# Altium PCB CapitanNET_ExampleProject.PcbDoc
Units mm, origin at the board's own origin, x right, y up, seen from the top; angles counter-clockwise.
Board outline 171.38 x 171.4 mm, 6 copper layers (Top Layer, Mid-Layer 1, Mid-Layer 2, Mid-Layer 3, Mid-Layer 4, Bottom Layer), stack 1.53 mm thick; 13 components, 61 nets, 307 pads, 51 vias.
Unrouted connection lines stored in the file: 9.
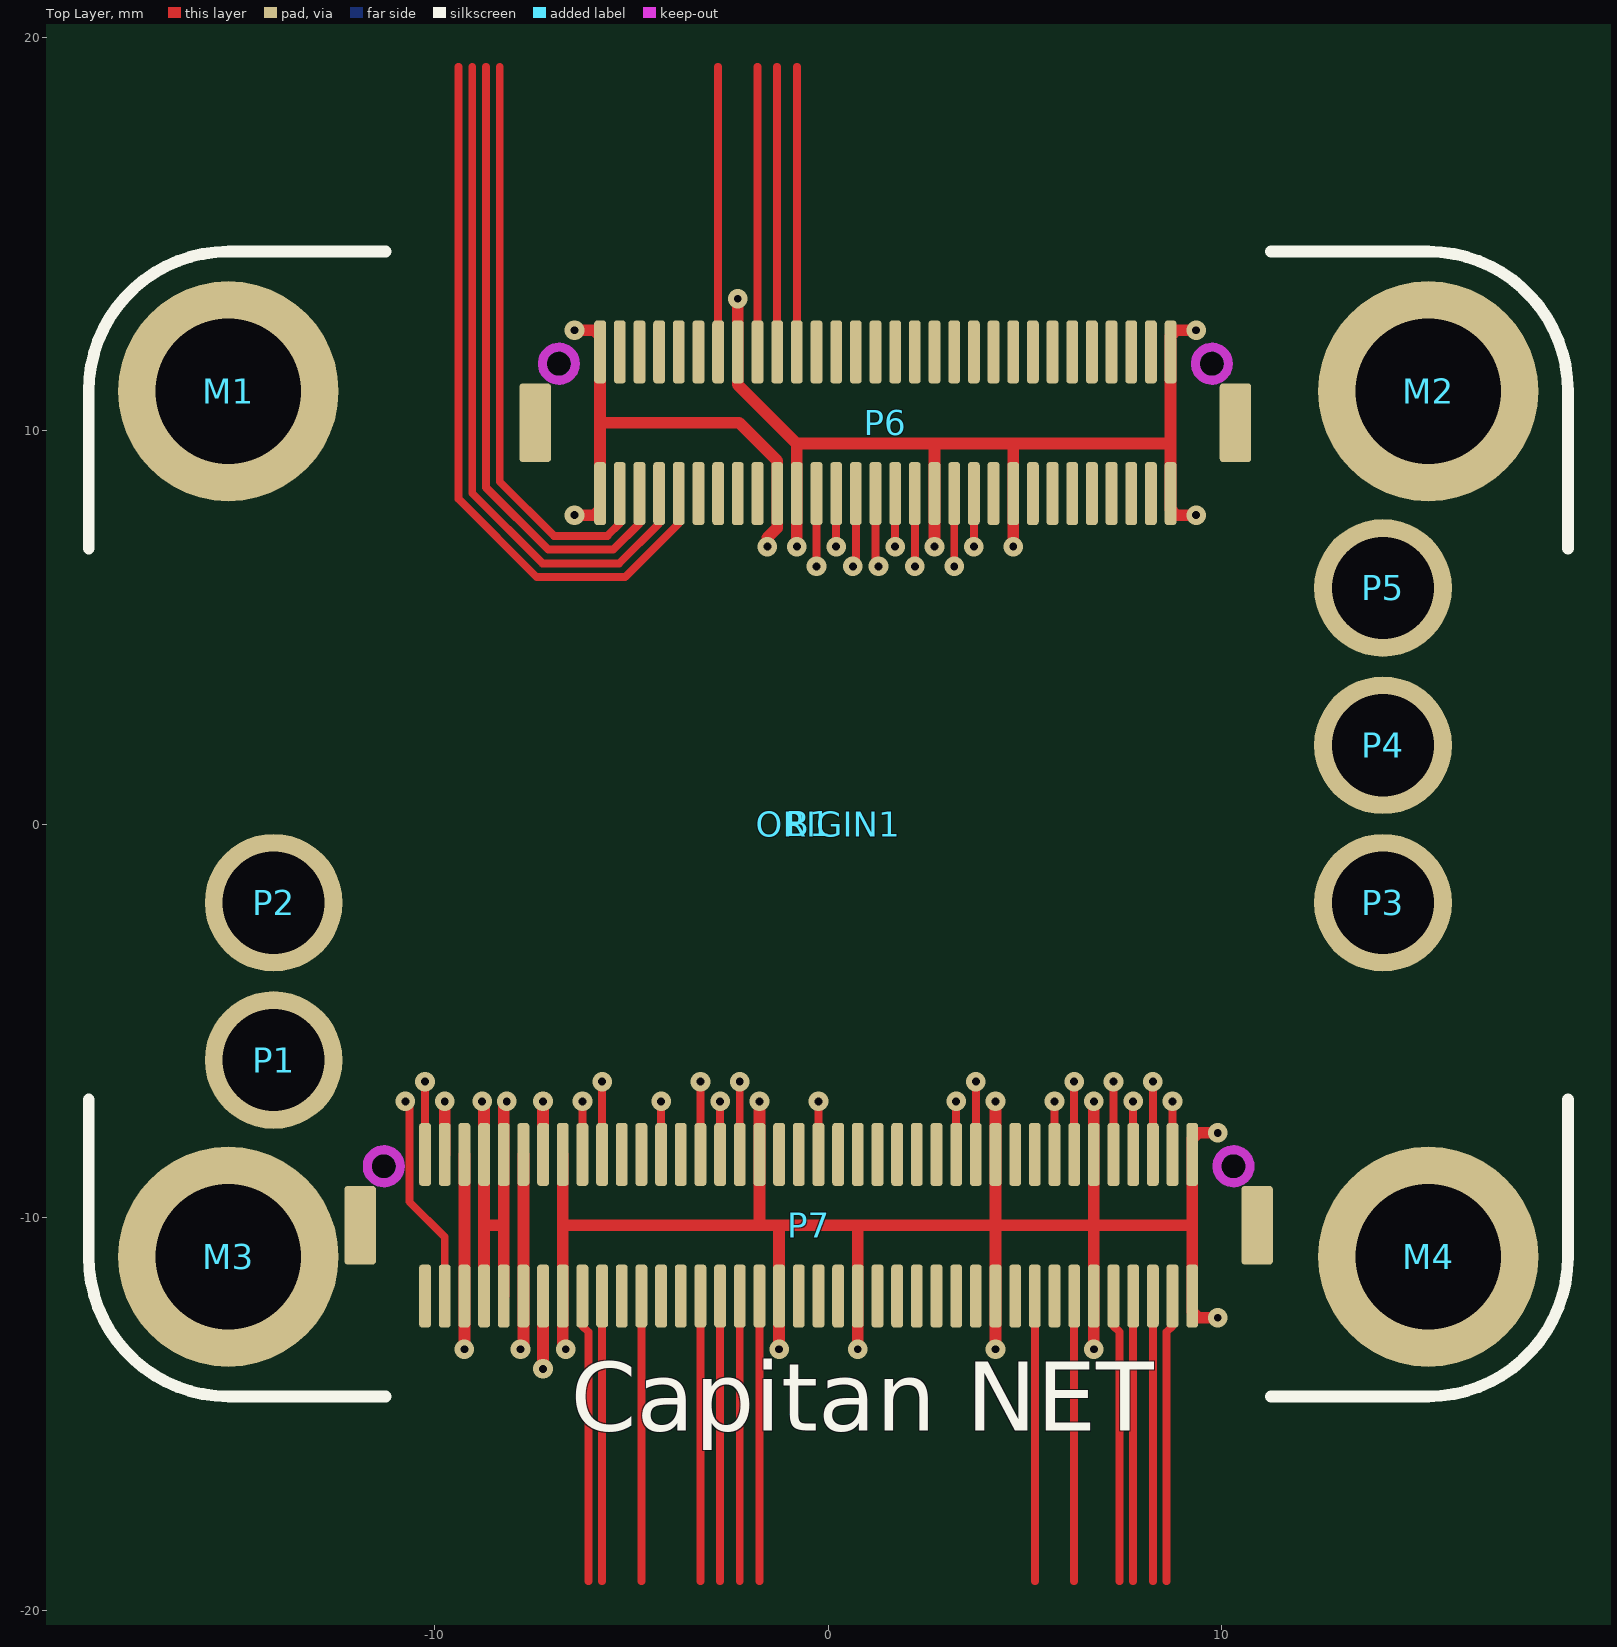
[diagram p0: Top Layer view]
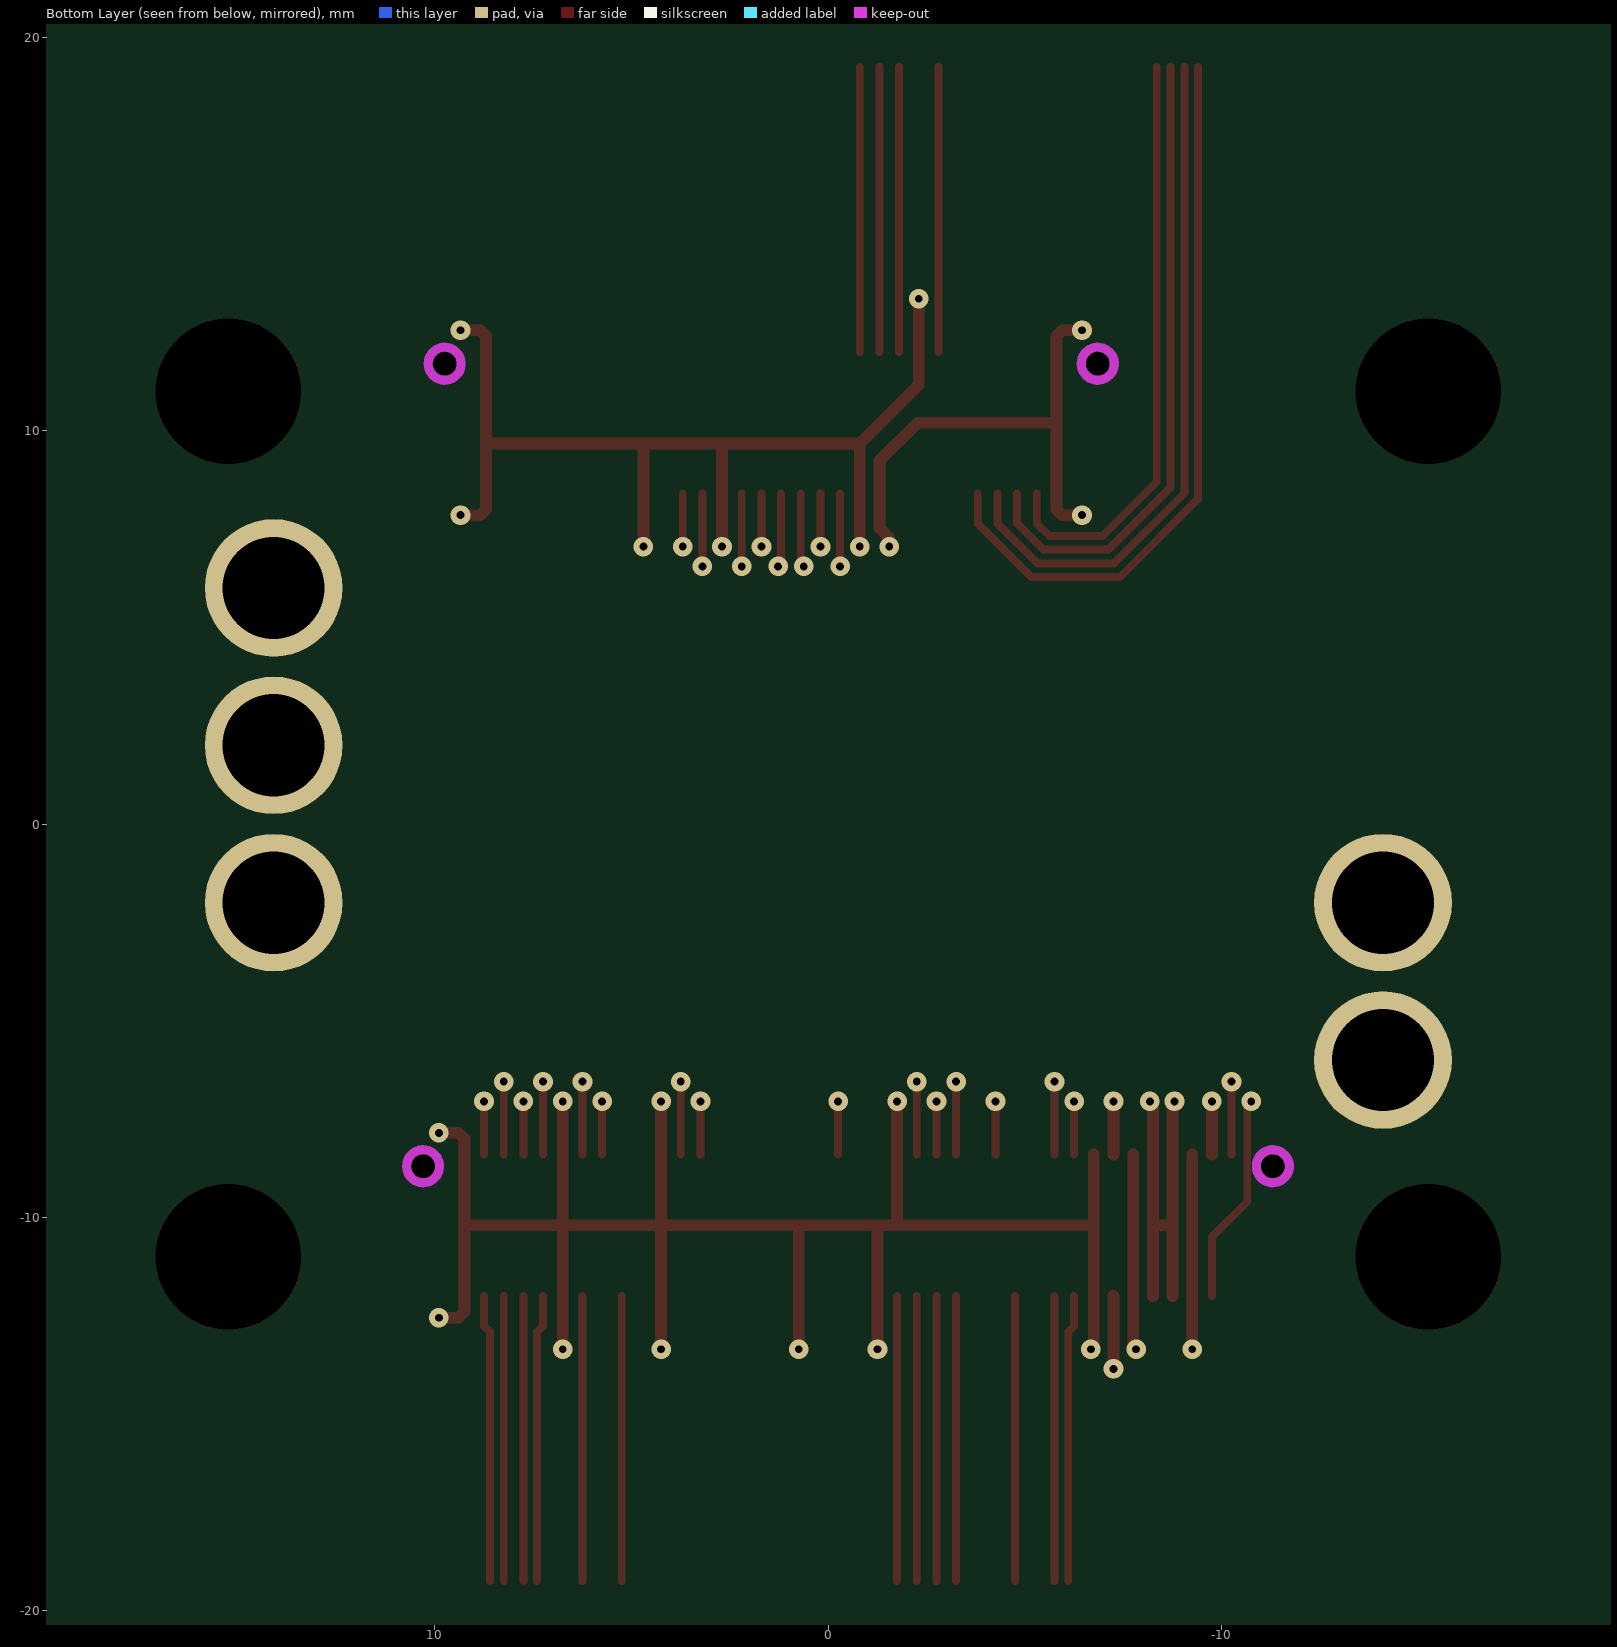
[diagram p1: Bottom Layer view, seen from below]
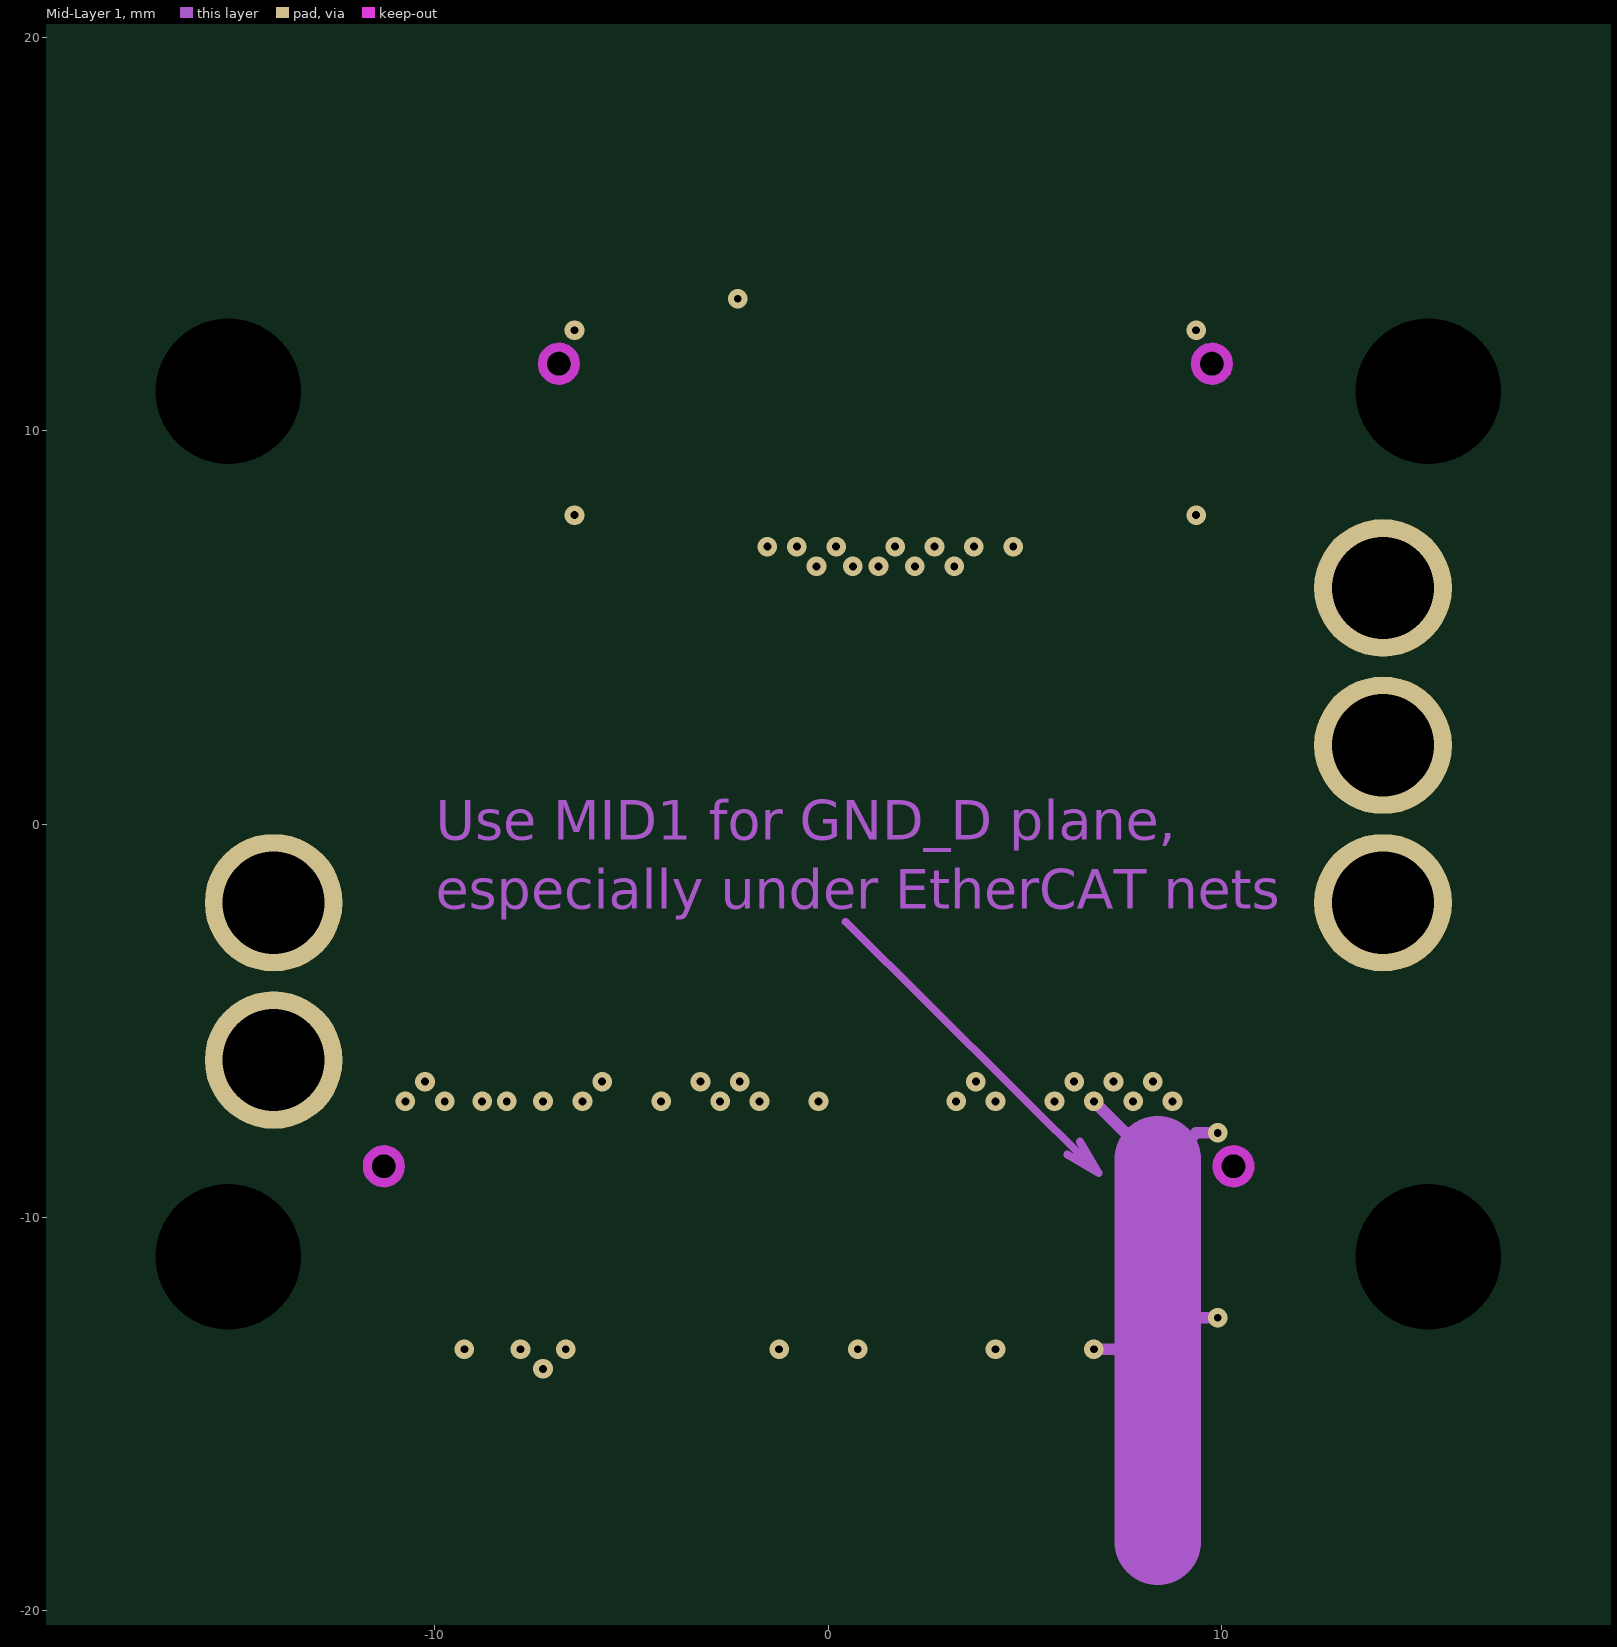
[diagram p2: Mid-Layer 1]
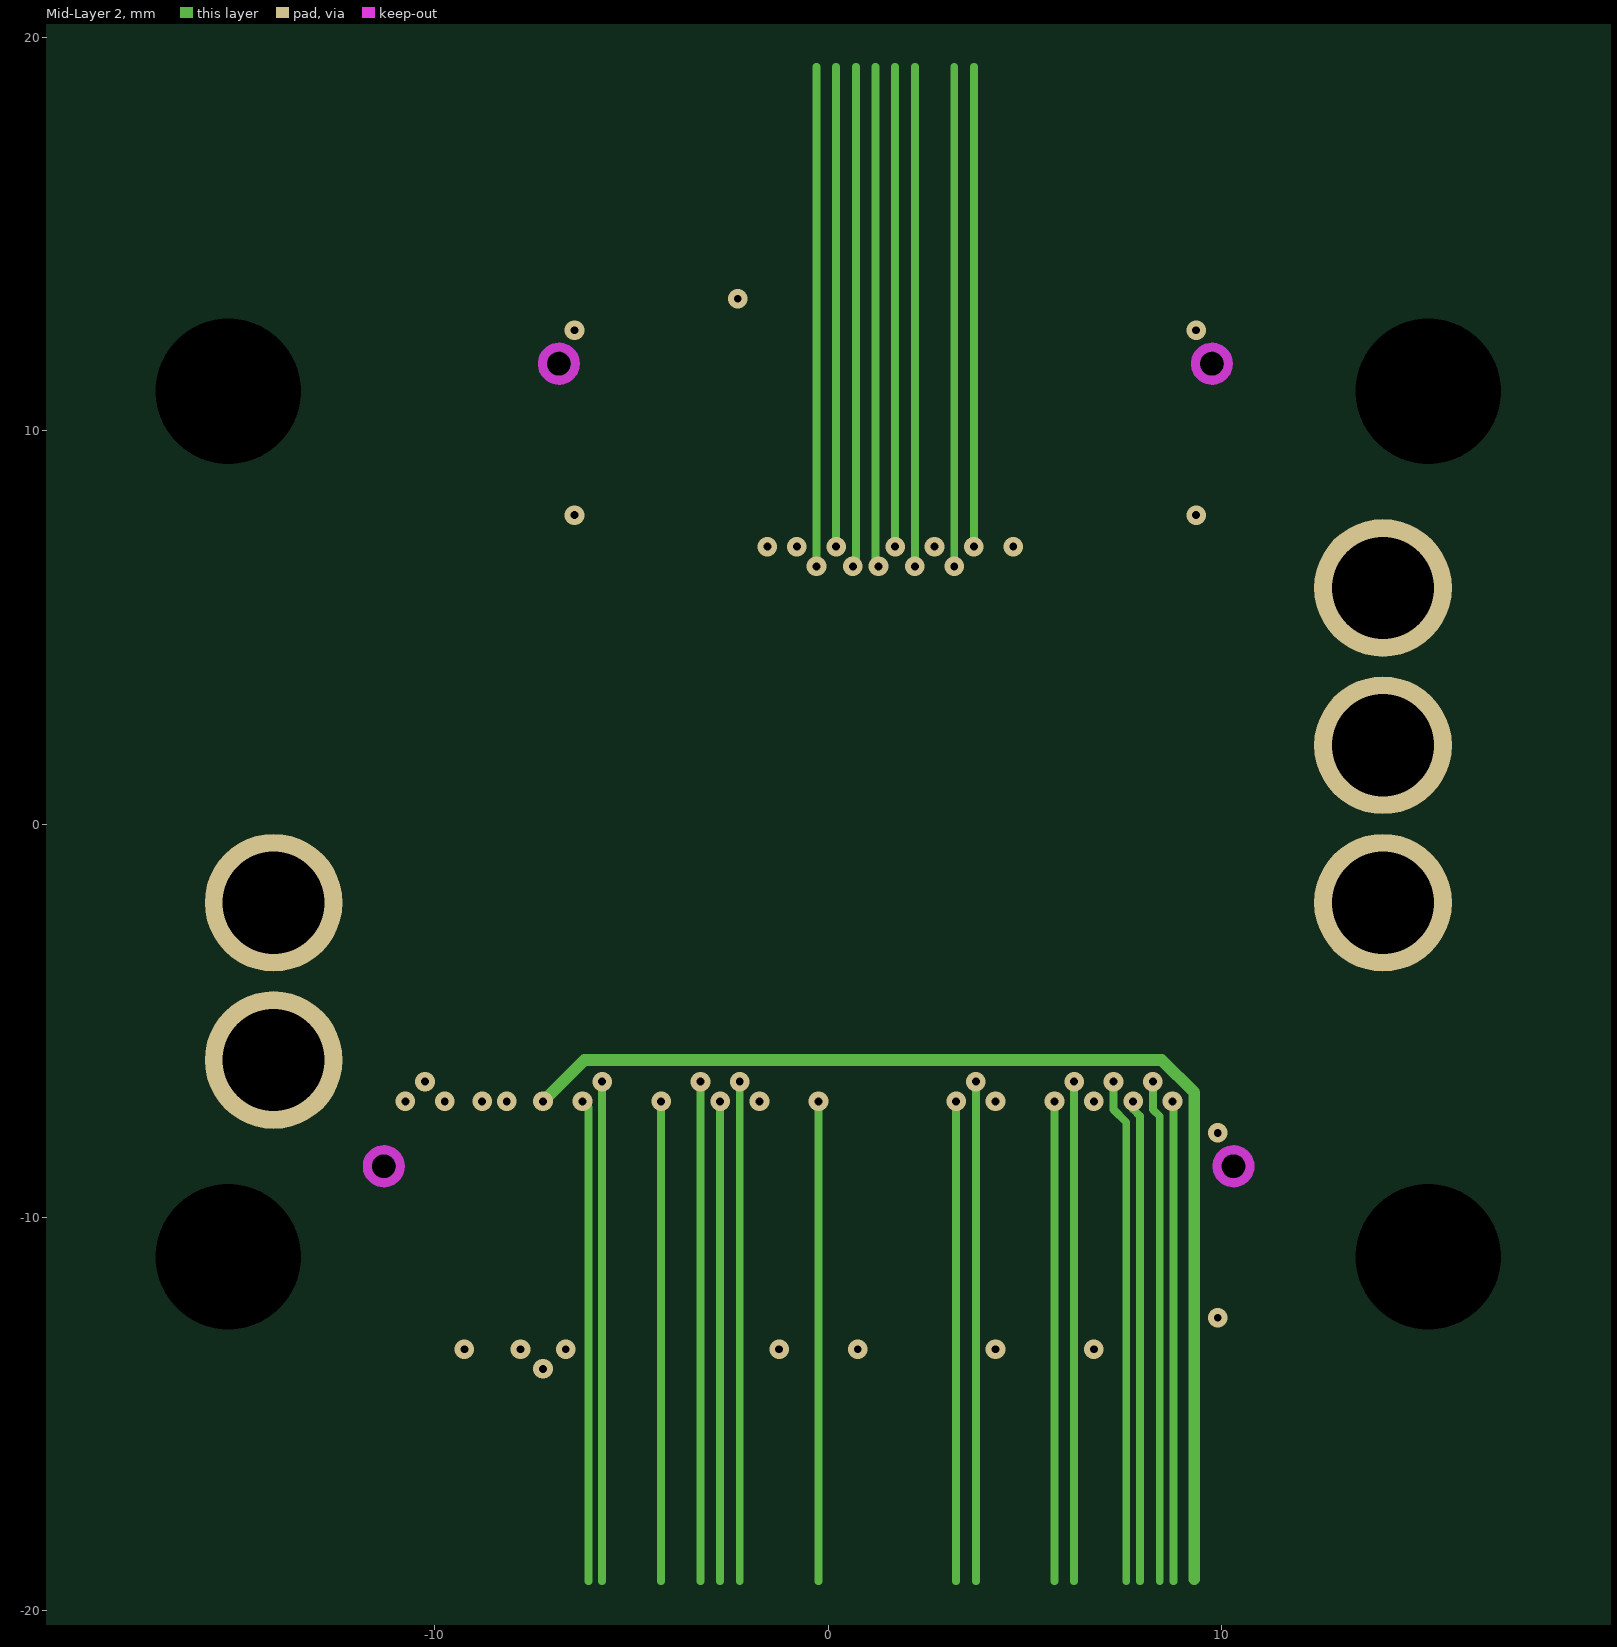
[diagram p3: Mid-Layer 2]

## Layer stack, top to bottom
Top Solder: solder mask 0.01, Solder Resist, Dk 3.5
Top Layer: signal copper 0.035
Dielectric1: prepreg 0.13, FR-4, Dk 4.8
Mid-Layer 1: signal copper 0.07
Dielectric2: core 0.35, FR-4, Dk 4.8
Mid-Layer 2: signal copper 0.07
Dielectric3: prepreg 0.22, FR-4, Dk 4.8
Mid-Layer 3: signal copper 0.07
Dielectric4: core 0.35, FR-4, Dk 4.8
Mid-Layer 4: signal copper 0.07
Dielectric5: prepreg 0.13, FR-4, Dk 4.8
Bottom Layer: signal copper 0.035
Bottom Solder: solder mask 0.01, Solder Resist, Dk 3.5

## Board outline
-87.181,-84.732 84.194,-84.732 84.194,86.668 -87.181,86.668

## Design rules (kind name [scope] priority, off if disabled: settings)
AssemblyTestPointUsage [All] p1 off: valid=2
AssemblyTestpoint [All] p1 off: testpointundercomponent=TRUE minsize=1.016 maxsize=2.54 preferedsize=1.524 minholesize=0 maxholesize=1.016 preferedholesize=0.813 testpointgrid=0.025 usegrid=TRUE gridtolerance=0 allowsidetop=TRUE allowsidebottom=TRUE
Clearance "Keepout clearance" [All vs OnLayer('Keep-Out Layer') Or IsKeepOut Or Keepout] p1: gap=0.001 ignorepadtopadclearanceinfootprint=FALSE
Clearance HV [InNetClass('HighVoltage') vs OnOutside And NOT InNetClass('HighVoltageFloating')] p2: gap=0.5 ignorepadtopadclearanceinfootprint=TRUE
Clearance Clearance_PE [InNetClass('ProtectiveEarth')] p3: gap=0.5 ignorepadtopadclearanceinfootprint=TRUE
Clearance General [All] p4: gap=0.15 ignorepadtopadclearanceinfootprint=TRUE
ComponentClearance ComponentClearance_Excluded [All vs InComponent ('B1') OR InComponent('P1') OR InComponent('P2') OR InComponent('P3') OR InComponent('P4') OR InComponent('P5') OR InComponent('P6') OR InComponent('P7') OR InComponent('H1') OR InComponent('H2') OR InComponent('H3') OR InComponent('H4') OR InComponent('H5') OR InComponent('M1') OR InComponent('M2') OR InComponent('M3') OR InComponent('M4')] p1: gap=0 collisioncheckmode=3 verticalgap=0 showdistances=FALSE
ComponentClearance [All] p2: gap=0.2 collisioncheckmode=3 verticalgap=0.2 showdistances=FALSE
DiffPairsRouting [All] p1: maxlimit=1 minlimit=0.15 mostfreqgap=0.2 toplayer_minwidth=0.15 toplayer_maxwidth=0.3 toplayer_prefwidth=0.2 midlayer1_minwidth=0.15 midlayer1_maxwidth=0.3 midlayer1_prefwidth=0.2 midlayer2_minwidth=0.15 midlayer2_maxwidth=0.3 midlayer2_prefwidth=0.2 midlayer3_minwidth=0.15 midlayer3_maxwidth=0.3 midlayer3_prefwidth=0.2 midlayer4_minwidth=0.15 midlayer4_maxwidth=0.3 midlayer4_prefwidth=0.2 bottomlayer_minwidth=0.15 bottomlayer_maxwidth=0.3 bottomlayer_prefwidth=0.2 maxuncoupledlength=12.7
FabricationTestPointUsage [All] p1 off: valid=0 allowmultiple=FALSE
FabricationTestpoint [All] p1 off: side=3 testpointundercomponent=TRUE minsize=1.016 maxsize=2.54 preferedsize=1.524 minholesize=0 maxholesize=1.016 preferedholesize=0.813 testpointgrid=0.025 allowsidetop=TRUE allowsidebottom=TRUE usegrid=TRUE gridtolerance=0
FanoutControl Fanout_BGA [IsBGA] p1 off: bgadir=Out bgaviamode=Centered fanoutstyle=Auto fanoutdirection=Alternating viagrid=0.025 // Fanout_BGA (Default Rule)
FanoutControl Fanout_LCC [IsLCC] p2 off: bgadir=Out bgaviamode=Centered fanoutstyle=Auto fanoutdirection=Alternating viagrid=0.025 // Fanout_LCC (Default Rule)
FanoutControl Fanout_SOIC [IsSOIC] p3 off: bgadir=Out bgaviamode=Centered fanoutstyle=Auto fanoutdirection=Alternating viagrid=0.025 // Fanout_SOIC (Default Rule)
FanoutControl Fanout_Small [(CompPinCount < 5)] p4 off: bgadir=Out bgaviamode=Centered fanoutstyle=Auto fanoutdirection=OutThenIn viagrid=0.025 // Fanout_Small (Default Rule)
FanoutControl Fanout_Default [All] p5 off: bgadir=Out bgaviamode=Centered fanoutstyle=Auto fanoutdirection=Alternating viagrid=0.025 // Fanout_Default (Default Rule)
Height [All] p1: minheight=0 maxheight=30 prefheight=12.7
HoleSize [All] p1: absolutevalues=TRUE maxlimit=5 minlimit=0.1 maxpercent=80.000 minpercent=20.000
HoleToHoleClearance [All] p1: gap=0.3 allowstackedmicrovias=FALSE
MinimumAnnularRing [All] p1: minimumring=0.1
MinimumSolderMaskSliver [All] p1: minsoldermaskwidth=0.07
NetAntennae [All] p1: netantennaetolerance=2
PlaneClearance [All] p1: clearance=0.25
PlaneConnect [All] p1: planeconnectstyle=Relief reliefexpansion=0.5 reliefentries=4 reliefconductorwidth=0.25 reliefairgap=0.25
PolygonConnect [All] p1: connectstyle=Direct reliefconductorwidth=0.25 reliefentries=4 polygonreliefangle="90 Angle" airgapwidth=0.25
RoomDefinition U_CapitanNET_Module [InComponentClass('U_CapitanNET_Module')] p1: confinementstyle=ConfineIn formatcopy=TRUE lockcomponents=FALSE outline -155.261,-141.812 -104.461,-141.812 -104.461,-116.412 -155.261,-116.412
RoutingVias [All] p1: holewidth=0.2 width=0.6 viastyle="Through Hole" minholewidth=0.1 minwidth=0.3 maxholewidth=1 maxwidth=1.5
SilkToSilkClearance [All] p1 off: silktosilkclearance=0.1
SilkToSolderMaskClearance SilkscreenOverComponentPads [IsPad] p1 off: minsilkscreentomaskgap=0.05 clearancetoexposedcopper=TRUE
SolderMaskExpansion [All] p1: expansion=0.05 istentingtop=FALSE
UnRoutedNet [All] p1: checkbadconnections=TRUE
Width [All] p1: maxlimit=80 minlimit=0.15 preferedwidth=0.2 checkconnectedcopper=TRUE
9 further rules are at their usual default settings.

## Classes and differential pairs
component class Top: ORIGIN1
net class ProtectiveEarth: PE1 PE2 PE3 PE4
net class HighVoltage: GND_P PH_A PH_B PH_C POW_SUP
net class HighCurrent: GND_P PH_A PH_B PH_C POW_SUP
component class U_CapitanNET_Module: B1 M1 M2 M3 M4 P1 P2 P3 P4 P5 P6 P7

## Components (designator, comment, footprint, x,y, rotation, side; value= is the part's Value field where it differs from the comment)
B1 "Capitan_NET" CAPITAN_NET 0,0 r0 top value=-
M1 "Part Number" WURTH_9774030951R -15.25,11 r0 top value=-
M2 "Part Number" WURTH_9774030951R 15.25,11 r0 top value=-
M3 "Part Number" WURTH_9774030951R -15.25,-11 r0 top value=-
M4 "WURTH_9774030951R" WURTH_9774030951R 15.25,-11 r0 top value=-
ORIGIN1 "ORIGIN" ORIGIN 0,0 r0 top value=-
P1 "Part Number" MillMax_9801-0-15-15-23-27-10-0 -14.1,-6 r0 top value=-
P2 "Part Number" MillMax_9801-0-15-15-23-27-10-0 -14.1,-2 r0 top value=-
P3 "Part Number" MillMax_9801-0-15-15-23-27-10-0 14.1,-2 r0 top value=-
P4 "Part Number" MillMax_9801-0-15-15-23-27-10-0 14.1,2 r0 top value=-
P5 "Part Number" MillMax_9801-0-15-15-23-27-10-0 14.1,6 r0 top value=-
P6 "HIROSE_DF12NB_(3.0)-60DS-0.5V_(51)" HIROSE_DF12NB(3.0)-60DS-0.5V(51) 1.45,10.2 r0 top value=-
P7 "HIROSE_DF12NB(3.0)-80DS-0.5V(51)" HIROSE_DF12NB(3.0)-80DS-0.5V(51) -0.5,-10.2 r0 top value=-

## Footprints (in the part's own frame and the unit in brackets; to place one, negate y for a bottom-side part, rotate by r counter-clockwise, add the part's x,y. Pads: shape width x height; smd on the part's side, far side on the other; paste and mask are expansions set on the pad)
CAPITAN_NET [mm] "Capitan NET 3D model + Pads + Connectors position"
  rrect20% 0.8x2 on Mech5: 0(-11.9,-10.2) 0(-7.45,10.2) 0(10.35,10.2) 0(10.9,-10.2)
  rrect50% 0.3x1.6 on Mech5: 1(-10.25,-8.4) 1(-5.8,12) 2(-10.25,-12) 2(-5.8,8.4) 3(-9.75,-8.4) 3(-5.3,12) 4(-9.75,-12) 4(-5.3,8.4) 5(-9.25,-8.4) 5(-4.8,12) 6(-9.25,-12) 6(-4.8,8.4) 7(-8.75,-8.4) 7(-4.3,12) 8(-8.75,-12) 8(-4.3,8.4) 9(-8.25,-8.4) 9(-3.8,12) 10(-8.25,-12) 10(-3.8,8.4) 11(-7.75,-8.4) 11(-3.3,12) 12(-7.75,-12) 12(-3.3,8.4) 13(-7.25,-8.4) 13(-2.8,12) 14(-7.25,-12) 14(-2.8,8.4) 15(-6.75,-8.4) 15(-2.3,12) 16(-6.75,-12) 16(-2.3,8.4) 17(-6.25,-8.4) 17(-1.8,12) 18(-6.25,-12) 18(-1.8,8.4) 19(-5.75,-8.4) 19(-1.3,12) 20(-5.75,-12) 20(-1.3,8.4) 21(-5.25,-8.4) 21(-0.8,12) 22(-5.25,-12) 22(-0.8,8.4) 23(-4.75,-8.4) 23(-0.3,12) 24(-4.75,-12) 24(-0.3,8.4) 25(-4.25,-8.4) 25(0.2,12) 26(-4.25,-12) 26(0.2,8.4) 27(-3.75,-8.4) 27(0.7,12) 28(-3.75,-12) 28(0.7,8.4) 29(-3.25,-8.4) 29(1.2,12) 30(-3.25,-12) 30(1.2,8.4) 31(-2.75,-8.4) 31(1.7,12) 32(-2.75,-12) 32(1.7,8.4) 33(-2.25,-8.4) 33(2.2,12) 34(-2.25,-12) 34(2.2,8.4) 35(-1.75,-8.4) 35(2.7,12) 36(-1.75,-12) 36(2.7,8.4) 37(-1.25,-8.4) 37(3.2,12) 38(-1.25,-12) 38(3.2,8.4) 39(-0.75,-8.4) 39(3.7,12) 40(-0.75,-12) 40(3.7,8.4) 41(-0.25,-8.4) 41(4.2,12) 42(-0.25,-12) 42(4.2,8.4) 43(0.25,-8.4) 43(4.7,12) 44(0.25,-12) 44(4.7,8.4) 45(0.75,-8.4) 45(5.2,12) 46(0.75,-12) 46(5.2,8.4) 47(1.25,-8.4) 47(5.7,12) 48(1.25,-12) 48(5.7,8.4) 49(1.75,-8.4) 49(6.2,12) 50(1.75,-12) 50(6.2,8.4) 51(2.25,-8.4) 51(6.7,12) 52(2.25,-12) 52(6.7,8.4) 53(2.75,-8.4) 53(7.2,12) 54(2.75,-12) 54(7.2,8.4) 55(3.25,-8.4) 55(7.7,12) 56(3.25,-12) 56(7.7,8.4) 57(3.75,-8.4) 57(8.2,12) 58(3.75,-12) 58(8.2,8.4) 59(4.25,-8.4) 59(8.7,12) 60(4.25,-12) 60(8.7,8.4) 61(4.75,-8.4) 62(4.75,-12) 63(5.25,-8.4) 64(5.25,-12) 65(5.75,-8.4) 66(5.75,-12) 67(6.25,-8.4) 68(6.25,-12) 69(6.75,-8.4) 70(6.75,-12) 71(7.25,-8.4) 72(7.25,-12) 73(7.75,-8.4) 74(7.75,-12) 75(8.25,-8.4) 76(8.25,-12) 77(8.75,-8.4) 78(8.75,-12) 79(9.25,-8.4) 80(9.25,-12)
  silkscreen extent -18.8,-14.55 18.8,14.55, body extent -17.25,-13 17.25,13, height 11
HIROSE_DF12NB(3.0)-60DS-0.5V(51) [mm] "CONN HEADER BLACK 60POS 5MM SMD 0.5MM"
  rrect50% 0.3x1.6 smd: 1(-7.25,1.8) 2(-7.25,-1.8) 3(-6.75,1.8) 4(-6.75,-1.8) 5(-6.25,1.8) 6(-6.25,-1.8) 7(-5.75,1.8) 8(-5.75,-1.8) 9(-5.25,1.8) 10(-5.25,-1.8) 11(-4.75,1.8) 12(-4.75,-1.8) 13(-4.25,1.8) 14(-4.25,-1.8) 15(-3.75,1.8) 16(-3.75,-1.8) 17(-3.25,1.8) 18(-3.25,-1.8) 19(-2.75,1.8) 20(-2.75,-1.8) 21(-2.25,1.8) 22(-2.25,-1.8) 23(-1.75,1.8) 24(-1.75,-1.8) 25(-1.25,1.8) 26(-1.25,-1.8) 27(-0.75,1.8) 28(-0.75,-1.8) 29(-0.25,1.8) 30(-0.25,-1.8) 31(0.25,1.8) 32(0.25,-1.8) 33(0.75,1.8) 34(0.75,-1.8) 35(1.25,1.8) 36(1.25,-1.8) 37(1.75,1.8) 38(1.75,-1.8) 39(2.25,1.8) 40(2.25,-1.8) 41(2.75,1.8) 42(2.75,-1.8) 43(3.25,1.8) 44(3.25,-1.8) 45(3.75,1.8) 46(3.75,-1.8) 47(4.25,1.8) 48(4.25,-1.8) 49(4.75,1.8) 50(4.75,-1.8) 51(5.25,1.8) 52(5.25,-1.8) 53(5.75,1.8) 54(5.75,-1.8) 55(6.25,1.8) 56(6.25,-1.8) 57(6.75,1.8) 58(6.75,-1.8) 59(7.25,1.8) 60(7.25,-1.8)
  round 0 hole 0.6 unplated: H1(-8.3,1.5) H2(8.3,1.5)
  rrect20% 0.8x2 smd: S1(-8.9,0) S2(8.9,0)
  Keep-Out Layer circle w0.23: c8.3,1.5 r0.42
  Keep-Out Layer circle w0.23: c-8.3,1.5 r0.42
  body extent -9.05,-2.3 9.05,2.3, height 2.2
HIROSE_DF12NB(3.0)-80DS-0.5V(51) [mm] "CONN HEADER 80POS 3MM SMD 0.5MM"
  rrect50% 0.3x1.6 smd paste-0.02 mask+0.05: 1(-9.75,1.8) 2(-9.75,-1.8) 3(-9.25,1.8) 4(-9.25,-1.8) 5(-8.75,1.8) 6(-8.75,-1.8) 7(-8.25,1.8) 8(-8.25,-1.8) 9(-7.75,1.8) 10(-7.75,-1.8) 11(-7.25,1.8) 12(-7.25,-1.8) 13(-6.75,1.8) 14(-6.75,-1.8) 15(-6.25,1.8) 16(-6.25,-1.8) 17(-5.75,1.8) 18(-5.75,-1.8) 19(-5.25,1.8) 20(-5.25,-1.8) 21(-4.75,1.8) 22(-4.75,-1.8) 23(-4.25,1.8) 24(-4.25,-1.8) 25(-3.75,1.8) 26(-3.75,-1.8) 27(-3.25,1.8) 28(-3.25,-1.8) 29(-2.75,1.8) 30(-2.75,-1.8) 31(-2.25,1.8) 32(-2.25,-1.8) 33(-1.75,1.8) 34(-1.75,-1.8) 35(-1.25,1.8) 36(-1.25,-1.8) 37(-0.75,1.8) 38(-0.75,-1.8) 39(-0.25,1.8) 40(-0.25,-1.8) 41(0.25,1.8) 42(0.25,-1.8) 43(0.75,1.8) 44(0.75,-1.8) 45(1.25,1.8) 46(1.25,-1.8) 47(1.75,1.8) 48(1.75,-1.8) 49(2.25,1.8) 50(2.25,-1.8) 51(2.75,1.8) 52(2.75,-1.8) 53(3.25,1.8) 54(3.25,-1.8) 55(3.75,1.8) 56(3.75,-1.8) 57(4.25,1.8) 58(4.25,-1.8) 59(4.75,1.8) 60(4.75,-1.8) 61(5.25,1.8) 62(5.25,-1.8) 63(5.75,1.8) 64(5.75,-1.8) 65(6.25,1.8) 66(6.25,-1.8) 67(6.75,1.8) 68(6.75,-1.8) 69(7.25,1.8) 70(7.25,-1.8) 71(7.75,1.8) 72(7.75,-1.8) 73(8.25,1.8) 74(8.25,-1.8) 75(8.75,1.8) 76(8.75,-1.8) 77(9.25,1.8) 78(9.25,-1.8) 79(9.75,1.8) 80(9.75,-1.8)
  round 0 hole 0.6 unplated: H1(-10.8,1.5) H2(10.8,1.5)
  rrect20% 0.8x2 smd: S1(-11.4,0) S2(11.4,0)
  Keep-Out Layer circle w0.23: c10.8,1.5 r0.42
  Keep-Out Layer circle w0.23: c-10.8,1.5 r0.42
  body extent -11.55,-2.3 11.55,2.3, height 2.2
MillMax_9801-0-15-15-23-27-10-0 [mm]
  round 3.5 hole 2.6: 1(0,0)
  body extent -1.52,-1.52 1.52,1.52, height 1.78
ORIGIN [mm] "Origin of coordinate axes for pick and place"
  round 0.5 on Mech10 paste+0 mask+0: 1(0,0) 1(0,0)
  round 0.5 on Mech16 paste+0 mask+0: 1(0,0) 1(0,0)
  round 0.5 on Mech11 paste+0 mask+0: 1(0,0) 1(0,0)
  body extent 0,0 0,0
WURTH_9774030951R [mm] "M2.5 SPACER Thread Internal, Length 3mm"
  round 5.6 / inner round 0 / far side round 0 hole 3.7 unplated paste-403.566: 1(0,0)
  body extent -2.55,-2.55 2.55,2.55, height 3.01

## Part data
B1: "Capitan NET high-performance Servo Drive from Ingenia Motion Control.", AlternativeManufacturer=Ingenia, ManufacturerPN=CAP-NET-E, Package Type=-, TemperatureMaxC=85, TemperatureMinC=-40
M1 M2 M3 M4: library part SPACER_SMD_ROUND_M2.5x3mm_NO_THREAD, "Round SMD standoff M2.5 3mm height No Threaded Steel", ManufacturerName="Wurth Electronics Inc", ManufacturerPN=9774030951R, Package Name="SPACER M2.5 SMD REEL 3MM", Package Type=SM, Supplier Part Number 1=732-7086-1-ND, TemperatureMaxC=200, TemperatureMinC=-40
ORIGIN1: "Origin of coordinate axes for pick and place", ManufacturerName=-, TemperatureMaxC=200, TemperatureMinC=-60
P1 P2 P3 P4 P5: library part MillMax_9801-0-15-15-23-27-10-0, "1pin, receptacle for MillMax 6142, blind end", ManufacturerName=MillMax, ManufacturerPN=9801-0-15-15-23-27-10-0, Package Type=TH, Supplier Part Number 1=ED1006-ND, TemperatureMaxC=125, TemperatureMinC=-55
P6: "Connector SMD Mezzanine, Black 60 ways, 0.5mm pitch, 3mm stack height. Male", ManufacturerName=Hirose, ManufacturerPN=DF12NB(3.0)-60DS-0.5V(51), Package Name="SMD connector 60 ways male", Package Type=SM, Supplier Part Number 1=26-DF12NB(3.0)-60DS-0.5V(51)CT, TemperatureMaxC=125, TemperatureMinC=-55
P7: "Connector SMD Mezzanine, 80 ways, 0.5mm pitch, 3mm stack height. Male with metal fitting", AlternativeManufacturer=Hirose, ManufacturerPN=DF12NB(3.0)-80DS-0.5V(51), Package Name="SMD connector 80 ways male", Package Type=SM, Supplier Part Number 1=26-DF12NB(3.0)-80DS-0.5V(51), TemperatureMaxC=125, TemperatureMinC=-45

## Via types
v1: diameter 0.5, hole 0.2, Top Layer to Bottom Layer, 51 vias

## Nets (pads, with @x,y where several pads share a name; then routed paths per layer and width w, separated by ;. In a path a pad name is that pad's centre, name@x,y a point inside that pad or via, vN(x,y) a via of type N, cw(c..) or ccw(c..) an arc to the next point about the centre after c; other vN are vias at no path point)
+1.65V_REF: P7.4 | length 5.4
  Top Layer w0.2: v1(-10.75,-7.05) -10.65,-7.15 -10.65,-9.6 -9.75,-10.5 P7.4
+3.3V_D: P6.25 P6.29 P7.14 | length 1.8
  Top Layer w0.3: v1(-7.25,-13.85) P7.14
+3.3V_REF: P7.1 | length 1.8
  Top Layer w0.2: P7.1 v1(-10.25,-6.55)
+5V_D: P7.7 P7.8 P7.9 P7.10 | length 10.4
  Top Layer w0.3: P7.8 -8.75,-10.2 ; v1@-8.75,-7.05 P7.7 -8.75,-10.2 ; P7.10 -8.25,-10.2 ; v1@-8.25,-7.05 P7.9 -8.25,-10.2 ; -8.75,-10.2 -8.25,-10.2
  other v1: -8.8,-7.05 -8.175,-7.05
\ETH0_LED_LINK: P7.67 | length 14.5
  Top Layer w0.2: P7.67 v1(6.25,-6.55)
  Mid-Layer 2 w0.2: 6.25,-19.25 v1(6.25,-6.55)
\ETH1_LED_LINK: P7.68 | length 7.3
  Top Layer w0.2: 6.25,-19.25 P7.68
\STO1: P7.33 | length 14.5
  Top Layer w0.2: P7.33 v1(-2.25,-6.55)
  Mid-Layer 2 w0.2: -2.25,-19.25 v1(-2.25,-6.55)
\STO2: P7.34 | length 7.3
  Top Layer w0.2: -2.25,-19.25 P7.34
ABSENC1_CLK: P6.38 | length 14.5
  Top Layer w0.2: v1(3.2,6.55) P6.38
  Mid-Layer 2 w0.2: v1(3.2,6.55) 3.2,19.25
ABSENC1_DATA: P6.40 | length 13.5
  Top Layer w0.2: v1(3.7,7.05) P6.40
  Mid-Layer 2 w0.2: v1(3.7,7.05) 3.7,19.25
ABSENC2_CLK: P7.24 | length 7.3
  Top Layer w0.2: -4.75,-19.25 P7.24
ABSENC2_DATA: P7.25 | length 13.5
  Top Layer w0.2: P7.25 v1(-4.25,-7.05)
  Mid-Layer 2 w0.2: -4.25,-19.25 v1(-4.25,-7.05)
AN1_N: P6.6 | length 16.3
  Top Layer w0.2: -8.7,19.25 -8.7,8.555 -7.12,6.975 -5.465,6.975 -4.8,7.64 P6.6
AN1_P: P6.4 | length 15.1
  Top Layer w0.2: -8.35,19.25 -8.35,8.7 -6.975,7.325 -5.615,7.325 -5.3,7.64 P6.4
AN2_N: P6.10 | length 18.7
  Top Layer w0.2: -9.4,19.25 -9.4,8.265 -7.41,6.275 -5.165,6.275 -3.8,7.64 P6.10
AN2_P: P6.8 | length 17.5
  Top Layer w0.2: -9.05,19.25 -9.05,8.41 -7.265,6.625 -5.315,6.625 -4.3,7.64 P6.8
BOOT: P7.51
CAN_RX: P7.57 | length 14.5
  Top Layer w0.2: P7.57 v1(3.75,-6.55)
  Mid-Layer 2 w0.2: 3.75,-19.25 v1(3.75,-6.55)
CAN_TX: P7.55 | length 13.5
  Top Layer w0.2: P7.55 v1(3.25,-7.05)
  Mid-Layer 2 w0.2: 3.25,-19.25 v1(3.25,-7.05)
DIG_ENC_1A: P6.24 | length 14.5
  Top Layer w0.2: v1(-0.3,6.55) P6.24
  Mid-Layer 2 w0.2: v1(-0.3,6.55) -0.3,19.25
DIG_ENC_1B: P6.26 | length 13.5
  Top Layer w0.2: v1(0.2,7.05) P6.26
  Mid-Layer 2 w0.2: v1(0.2,7.05) 0.2,19.25
DIG_ENC_1Z: P6.28 | length 14.6
  Top Layer w0.2: v1(0.625,6.55) 0.7,6.625 P6.28
  Mid-Layer 2 w0.2: v1(0.625,6.55) 0.7,6.625 0.7,19.25
DIG_ENC_2A: P6.30 | length 14.6
  Top Layer w0.2: P6.30 1.2,6.625 v1(1.275,6.55)
  Mid-Layer 2 w0.2: 1.2,19.25 1.2,6.625 v1(1.275,6.55)
DIG_ENC_2B: P6.32 | length 13.5
  Top Layer w0.2: v1(1.7,7.05) P6.32
  Mid-Layer 2 w0.2: v1(1.7,7.05) 1.7,19.25
DIG_ENC_2Z: P6.34 | length 14.5
  Top Layer w0.2: v1(2.2,6.55) P6.34
  Mid-Layer 2 w0.2: v1(2.2,6.55) 2.2,19.25
ECAT_CAN_ERR: P7.64 | length 7.3
  Top Layer w0.2: 5.25,-19.25 P7.64
ECAT_CAN_RUN: P7.65 | length 13.5
  Top Layer w0.2: P7.65 v1(5.75,-7.05)
  Mid-Layer 2 w0.2: 5.75,-19.25 v1(5.75,-7.05)
FAULT_SIGNAL: P7.36 | length 7.3
  Top Layer w0.2: -1.75,-19.25 P7.36
GND_A: P6.1 P6.2 P6.20 P7.3 | length 14.4
  Top Layer w0.3: P7.3 v1(-9.75,-7.05) ; v1(-6.45,7.85) -5.95,7.85 -5.8,8 P6.2 -5.8,10.2 ; v1(-6.45,12.55) -5.95,12.55 -5.8,12.4 P6.1 -5.8,10.2 ; v1(-1.55,7.05) -1.55,7.275 -1.3,7.525 P6.20 -1.3,9.23 -2.27,10.2 -5.8,10.2
GND_D: P6.15 P6.22 P6.23 P6.27 P6.36 P6.44 P6.59 P6.60 P7.5 P7.6 P7.11 P7.12 P7.15 P7.16 P7.35 P7.38 P7.46 P7.59 P7.60 P7.69 P7.70 P7.79 P7.80 | length 103.7
  Top Layer w0.3: v1(-9.25,-13.35) P7.5 ; v1(-7.825,-13.35) -7.825,-13.296 -7.75,-13.221 P7.12 P7.11 ; P7.15 -6.75,-10.2 ; v1(-6.675,-13.35) -6.675,-13.296 -6.75,-13.221 P7.16 -6.75,-10.2 ; v1(-2.3,13.35) P6.15 -2.3,11.17 -0.8,9.67 ; v1(-1.75,-7.05) -1.75,-10.2 ; v1(-1.25,-13.35) -1.25,-10.2 ; v1(-0.8,7.05) P6.22 -0.8,9.67 ; v1(0.75,-13.35) 0.75,-10.2 ; v1(2.7,7.05) P6.36 2.7,9.67 ; v1(4.25,-13.35) 4.25,-10.2 ; 4.25,-10.15 v1(4.25,-7.05) ; v1(4.7,7.05) P6.44 4.7,9.67 ; v1(6.75,-13.35) 6.75,-10.2 ; v1(6.75,-7.05) 6.75,-10.2 ; v1(9.35,7.85) 8.85,7.85 8.7,8 P6.60 8.7,9.67 ; v1(9.35,12.55) 8.85,12.55 8.7,12.4 P6.59 8.7,9.67 ; v1(9.9,-12.55) 9.4,-12.55 9.25,-12.4 9.25,-10.2 ; v1(9.9,-7.85) 9.4,-7.85 9.25,-8 9.25,-10.2 ; -6.75,-10.2 -1.75,-10.2 ; -1.75,-10.2 -1.25,-10.2 ; -1.25,-10.2 0.75,-10.2 ; -0.8,9.67 2.7,9.67 ; 0.75,-10.2 4.25,-10.2 ; 2.7,9.67 4.7,9.67 ; 4.25,-10.2 6.75,-10.2 ; 4.7,9.67 8.7,9.67 ; 6.75,-10.2 9.25,-10.2
  Mid-Layer 1 w0.3: v1(6.75,-13.35) 7.45,-13.35 8.25,-12.55 8.375,-12.55 v1(9.9,-12.55) ; v1(6.75,-7.05) 7.55,-7.85 8.138,-7.85 8.744,-8.456 9.35,-7.85 v1(9.9,-7.85)
  Mid-Layer 1 w2.2: 8.375,-18.25 8.375,-12.7 ; 8.375,-12.975 8.375,-12.55 8.375,-8.525
GND_P: P2.1
GPI1: P7.18 | length 7.3
  Top Layer w0.2: P7.18 -6.25,-12.76 -6.1,-12.91 -6.1,-19.25
GPI2: P7.19 | length 14.5
  Top Layer w0.2: P7.19 v1(-5.75,-6.55)
  Mid-Layer 2 w0.2: -5.75,-19.25 v1(-5.75,-6.55)
GPI3: P7.20 | length 7.3
  Top Layer w0.2: -5.75,-19.25 P7.20
GPI4: P7.32 | length 7.3
  Top Layer w0.2: -2.75,-19.25 P7.32
GPO1: P7.29 | length 14.5
  Top Layer w0.2: P7.29 v1(-3.25,-6.55)
  Mid-Layer 2 w0.2: -3.25,-19.25 v1(-3.25,-6.55)
GPO2: P7.30 | length 7.3
  Top Layer w0.2: -3.25,-19.25 P7.30
GPO3: P7.31 | length 13.5
  Top Layer w0.2: P7.31 v1(-2.75,-7.05)
  Mid-Layer 2 w0.2: -2.75,-19.25 v1(-2.75,-7.05)
GPO4: P7.17 | length 13.6
  Top Layer w0.2: P7.17 v1(-6.25,-7.05)
  Mid-Layer 2 w0.2: v1(-6.25,-7.05) -6.1,-7.2 -6.1,-19.25
HALL_1: P6.17 | length 7.3
  Top Layer w0.2: P6.17 -1.8,19.25
HALL_2: P6.19 | length 7.3
  Top Layer w0.2: P6.19 -1.3,19.25
HALL_3: P6.21 | length 7.3
  Top Layer w0.2: P6.21 -0.8,19.25
MAGNETICS_CT: P7.13 | length 31.1
  Top Layer w0.3: P7.13 v1(-7.25,-7.05)
  Mid-Layer 2 w0.3: v1(-7.25,-7.05) -6.2,-6 8.478,-6 9.3,-6.822 9.3,-19.2
MOTOR_TEMP: P6.13 | length 7.3
  Top Layer w0.2: P6.13 -2.8,19.25
PE1: M1.1
PE2: M2.1
PE3: M3.1 P7.S1
PE4: M4.1
PH_A: P5.1
PH_B: P4.1
PH_C: P3.1
PHY0_RX_N: P7.77 | length 13.4
  Top Layer w0.2: P7.77 v1(8.75,-7.05)
  Mid-Layer 2 w0.2: v1@8.75,-7.131 v1(8.75,-7.05) ; 8.775,-19.25 v1@8.775,-7.281
PHY0_RX_P: P7.75 | length 14.6
  Top Layer w0.2: P7.75 v1(8.25,-6.55)
  Mid-Layer 2 w0.2: v1(8.25,-6.55) 8.25,-7.257 8.425,-7.432 8.425,-19.25
PHY0_TX_N: P7.73 | length 13.6
  Top Layer w0.2: P7.73 v1(7.75,-7.05)
  Mid-Layer 2 w0.2: v1(7.75,-7.05) 7.75,-7.252 7.925,-7.427 7.925,-19.25
PHY0_TX_P: P7.71 | length 14.7
  Top Layer w0.2: P7.71 v1(7.25,-6.55)
  Mid-Layer 2 w0.2: v1(7.25,-6.55) 7.25,-7.257 7.575,-7.582 7.575,-19.25
PHY1_RX_N: P7.78 | length 7.3
  Top Layer w0.2: 8.6,-19.25 8.6,-12.91 8.75,-12.76 P7.78
PHY1_RX_P: P7.76 | length 7.3
  Top Layer w0.2: 8.25,-19.25 P7.76
PHY1_TX_N: P7.74 | length 7.3
  Top Layer w0.2: 7.75,-19.25 P7.74
PHY1_TX_P: P7.72 | length 7.3
  Top Layer w0.2: P7.72 7.25,-12.76 7.4,-12.91 7.4,-19.25
POW_SUP: P1.1
PWM_BRAKE: P7.41 | length 13.5
  Top Layer w0.2: P7.41 v1(-0.25,-7.05)
  Mid-Layer 2 w0.2: -0.25,-19.25 v1(-0.25,-7.05)
pads on no net: B1.0 B1.1 B1.2 B1.3 B1.4 B1.5 B1.6 B1.7 B1.8 B1.9 B1.10 B1.11 B1.12 B1.13 B1.14 B1.15 B1.16 B1.17 B1.18 B1.19 B1.20 B1.21 B1.22 B1.23 B1.24 B1.25 B1.26 B1.27 B1.28 B1.29 B1.30 B1.31 B1.32 B1.33 B1.34 B1.35 B1.36 B1.37 B1.38 B1.39 B1.40 B1.41 B1.42 B1.43 B1.44 B1.45 B1.46 B1.47 B1.48 B1.49 B1.50 B1.51 B1.52 B1.53 B1.54 B1.55 B1.56 B1.57 B1.58 B1.59 B1.60 B1.61 B1.62 B1.63 B1.64 B1.65 B1.66 B1.67 B1.68 B1.69 B1.70 B1.71 B1.72 B1.73 B1.74 B1.75 B1.76 B1.77 B1.78 B1.79 B1.80 ORIGIN1.1 P6.3 P6.5 P6.7 P6.9 P6.11 P6.12 P6.14 P6.16 P6.18 P6.31 P6.33 P6.35 P6.37 P6.39 P6.41 P6.42 P6.43 P6.45 P6.46 P6.47 P6.48 P6.49 P6.50 P6.51 P6.52 P6.53 P6.54 P6.55 P6.56 P6.57 P6.58 P6.H1 P6.H2 P6.S1 P6.S2 P7.2 P7.21 P7.22 P7.23 P7.26 P7.27 P7.28 P7.37 P7.39 P7.40 P7.42 P7.43 P7.44 P7.45 P7.47 P7.48 P7.49 P7.50 P7.52 P7.53 P7.54 P7.56 P7.58 P7.61 P7.62 P7.63 P7.66 P7.H1 P7.H2 P7.S2
copper on no net: | length 10.9
  Mid-Layer 1 w0.2: 0.44,-2.485 6.875,-8.875 ; 6.075,-8.4 6.875,-8.875 ; 6.4,-8.075 6.875,-8.875

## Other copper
Mid-Layer 1:
  text "Use MID1 for GND_D plane," at -9.975,-0.4 h1
  text "especially under EtherCAT nets" at -9.975,-2.15 h1

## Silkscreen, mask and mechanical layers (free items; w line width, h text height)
Mechanical 15:
  circle w0.2: c9.75,11.7 r0.42
  circle w0.2: c10.3,-8.7 r0.42
  circle w0.2: c-6.85,11.7 r0.42
  circle w0.2: c-11.3,-8.7 r0.42
  text "← Holes for back compatibility →" at -6.402,11.997 h1.2
Drill Drawing:
  circle w0.254: c-42.578,30.322 r0.46
  lines w0.2: -43.9,27.17 45.49,27.17 ; -43.9,35.452 45.49,35.452 ; -38.587,25.1 -38.587,37.522 ; -34.21,25.1 -34.21,37.522 ; -24.645,25.1 -24.645,37.522 ; -20.525,25.1 -20.525,37.522 ; -14.529,25.1 -14.529,37.522 ; -3.153,25.1 -3.153,37.522 ; 1.76,25.1 1.76,37.522 ; 8.177,25.1 8.177,37.522 ; 18.643,25.1 18.643,37.522 ; 25.091,25.1 25.091,37.522 ; 35.114,25.1 35.114,37.522 ; -43.9,25.1 45.49,25.1 45.49,37.522 -43.9,37.522 -43.9,25.1
  lines w0.254: -43.039,28.021 -42.808,28.021 -42.578,27.791 -42.348,28.021 -42.118,28.021 -42.348,28.251 -42.118,28.481 -42.348,28.481 -42.578,28.712 -42.808,28.481 -43.039,28.481 -42.808,28.251 -43.039,28.021 ; -43.039,31.932 -42.118,31.932 -42.118,32.852 -43.039,32.852 -43.039,31.932 ; -43.039,34.922 -42.118,34.922 -42.578,34.002 -43.039,34.922
  text "Symbol" at -42.658,36.073 h1.2
  text "Count" at -37.966,36.073 h1.2
  text "Hole Size" at -33.589,36.073 h1.2
  text "Plated" at -24.024,36.073 h1.2
  text "Hole Type" at -19.903,36.073 h1.2
  text "Drill Layer Pair" at -13.908,36.073 h1.2
  text "Via/Pad" at -2.532,36.073 h1.2
  text "Pad Shape" at 2.381,36.073 h1.2
  text "Template" at 8.798,36.073 h1.2
  text "Description" at 19.264,36.073 h1.2
  text "Hole Tolerance (+)" at 25.712,36.073 h1.2
  text "Hole Tolerance (-)" at 35.735,36.073 h1.2
  text "4" at -37.966,34.002 h1
  text "23,62mil (0,600mm)" at -33.589,34.002 h1
  text "NPTH" at -24.024,34.002 h1
  text "Round" at -19.903,34.002 h1
  text "Top Layer - Bottom Layer" at -13.908,34.002 h1
  text "Pad" at -2.532,34.002 h1
  text "Rounded" at 2.381,34.002 h1
  text "c0hn60" at 8.798,34.002 h1
  text "4" at -37.966,31.932 h1
  text "145,67mil (3,700mm)" at -33.589,31.932 h1
  text "NPTH" at -24.024,31.932 h1
  text "Round" at -19.903,31.932 h1
  text "Top Layer - Bottom Layer" at -13.908,31.932 h1
  text "Pad" at -2.532,31.932 h1
  text "Rounded" at 2.381,31.932 h1
  text "c560hn370z0x0p40917" at 8.798,31.932 h1
  text "5" at -37.966,29.862 h1
  text "102,36mil (2,600mm)" at -33.589,29.862 h1
  text "PTH" at -24.024,29.862 h1
  text "Round" at -19.903,29.862 h1
  text "Top Layer - Bottom Layer" at -13.908,29.862 h1
  text "Pad" at -2.532,29.862 h1
  text "Rounded" at 2.381,29.862 h1
  text "c350h260" at 8.798,29.862 h1
  text "51" at -37.966,27.791 h1
  text "7,87mil (0,200mm)" at -33.589,27.791 h1
  text "PTH" at -24.024,27.791 h1
  text "Round" at -19.903,27.791 h1
  text "Top Layer - Bottom Layer" at -13.908,27.791 h1
  text "Via" at -2.532,27.791 h1
  text "Rounded" at 2.381,27.791 h1
  text "v50h20m40" at 8.798,27.791 h1
  text "64 Total" at -37.966,25.721 h1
